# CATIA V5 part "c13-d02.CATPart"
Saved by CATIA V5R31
Part number: Part1
Bounding box of the stored display mesh (mm): x -33 to 33, y -200.819 to 48, z -35 to 35
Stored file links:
  D:\PROJECTS\Project 2021\US EDITION\CATIA V5 6R 2021\Resources\Part Files\c13_catia_v5_6r2021_prt\c13_catia_v5-6r2021_figr_13-13\c13-d02.CATPart
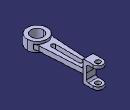
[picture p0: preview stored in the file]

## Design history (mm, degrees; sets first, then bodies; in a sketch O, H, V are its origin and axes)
Body1 (main body)
  Sketch1 on yz-plane, origin (0, 0, 0), H (0, 1, 0), V (0, 0, 1)
    line L1 (0, 0) -> (0, -35)
    point P1 (0, -35)
    line L2 (0, -35) -> (48, -35)
    point P2 (48, -35)
    line L3 (48, -35) -> (48, -25)
    point P3 (48, -25)
    line L4 (48, -25) -> (10, -25)
    point P4 (10, -25)
    line L5 (10, -25) -> (10, 0)
    point P5 (10, 0)
    point P6 (0, 0)
    point P7 (0, 0)
    point P8 (0, 35)
    point P9 (48, 35)
    point P10 (48, 25)
    point P11 (10, 25)
    point P12 (10, 0)
    point P13 (0, 0)
    line L6 (0, 0) -> (0, 35)
    line L7 (0, 35) -> (48, 35)
    line L8 (48, 35) -> (48, 25)
    line L9 (48, 25) -> (10, 25)
    line L10 (10, 25) -> (10, 0)
    length L8 = 10
    distance P3 L9 = 50
    length L2 = 48
    distance L10 L6 = 10
    vertical: L1 V, L3 V, L5 V
    horizontal: L2 H, L4 H
    symmetry: O P7 H, P1 P8 H, P2 P9 H, P3 P10 H, P4 P11 H, P5 P12 H, P6 P13 H, L1 L6 H, L2 L7 H, L3 L8 H, L4 L9 H, L5 L10 H
    coincidence: P13 P7, P12 P5, P6 P7
  Pad1: profile Sketch1, direction (1, 0, 0), length 16, mirrored extent
  Sketch2 on xy-plane, origin (0, 0, 0), H (1, 0, 0), V (0, 1, 0)
    circle A1 centre (0, -168) radius 33
    point P1 (0, -168)
    circle A2 centre (0, -168) radius 20
    distance P1 H = 168
    radius A1 = 33
    radius A2 = 20
    coincidence: P1 V
  Pad2: profile Sketch2, direction (0, 0, 1), length 16, mirrored extent
  Sketch3 on xy-plane, origin (0, 0, 0), H (1, 0, 0), V (0, 1, 0)
    line L1 (-16, 0) -> (-25, -146.4593)
    point P1 (-16, 0)
    point P2 (-25, -146.4593)
    line L2 (16, 0) -> (25, -146.4593)
    point P3 (16, 0)
    point P4 (25, -146.4593)
    reference projected line E1 (16, 48) -> (16, 0) from edge [face of Pad1 | face of Pad1]
    reference projected line E2 (-16, 48) -> (-16, 0) from edge [face of Pad1 | face of Pad1]
    projected circle E3 centre (0, -168) radius 33 from edge [face of Pad2 | face of Pad2]
    projected arc E4 centre (0, -168) radius 33 from (25, -146.4593) to (-25, -146.4593) ccw from edge [face of Pad2 | face of Pad2]
    line L3 (-16, 0) -> (16, 0)
    distance P4 P2 H = 50
    coincidence: P1 H, P3 H, P3 E1, P1 E2, P2 E3, P4 E3
    symmetry: P4 P2 V
    horizontal: L3 H
  Pad3: profile Sketch3, direction (0, 0, 1), length 8, mirrored extent
  Fillet1: radius 6, on edge [face of Pad1 | face of Pad3]; edge [face of Pad3 | face of Pad1]; edge [face of Pad1 | face of Pad1] (x2)
  Fillet2: radius 30, on edge [face of Pad3 | face of Pad2]; edge [face of Pad2 | face of Pad3]
  TritangentFillet1: Face1 face of Pad1, Face2 face of Pad1, RemoveFace face of Pad1
  TritangentFillet2: Face1 face of Pad1, Face2 face of Pad1, RemoveFace face of Pad1
  Sketch4 on face of Pad1, origin (2.8418, 32, 35), H (1, 0, 0), V (0, 1, 0)
    point P1 (-2.8418, 0)
    reference projected arc E1 centre (-2.8418, 0) radius 16 from (13.1582, 0) to (-18.8418, 0) ccw from edge [face of Pad1 | face of TritangentFillet1]
    concentricity: P1 E1
  Hole1: placed by Sketch4, at (0, 32, 35) direction (0, 0, -1), diameter 16, through (limit type 3)
  Sketch5 on face of Pad3, origin (0, 0, 8), H (1, 0, 0), V (0, 1, 0)
    construction line L1 (0, -25) -> (0, -115)
    point P1 (0, -25)
    line L2 (7, -25) -> (7, -115)
    line L3 (-7, -115) -> (-7, -25)
    arc A1 centre (0, -115) radius 7 from (7, -115) to (-7, -115) cw
    arc A2 centre (0, -25) radius 7 from (-7, -25) to (7, -25) cw
    distance P1 H = 25
    length L1 = 90
    radius A1 = 7
    coincidence: P1 V
    vertical: L1 V
    tangency: A1 L2, A2 L2, A1 L3, A2 L3
    parallelism: L1 L2
  Pocket1: profile Sketch5, direction (0, 0, -1), through (limit type 3)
